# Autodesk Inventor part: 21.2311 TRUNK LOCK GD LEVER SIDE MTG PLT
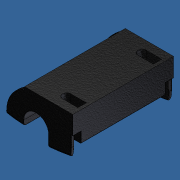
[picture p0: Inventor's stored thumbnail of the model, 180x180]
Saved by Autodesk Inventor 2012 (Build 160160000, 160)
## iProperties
Created: 2014-09
Part Number: 21.2311 TRUNK LOCK GD LEVER SIDE MTG PLT
Material: AL 6061-T6
Document SubType Name: Modeling
Designer: Admin
Density: 2.7 g/cm^3
Mass: 141.116 g
Surface Area: 166.843 cm^2
Volume: 52.2653 cm^3
Author: Admin
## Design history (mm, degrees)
feature "Base1"
body "Solid1"
